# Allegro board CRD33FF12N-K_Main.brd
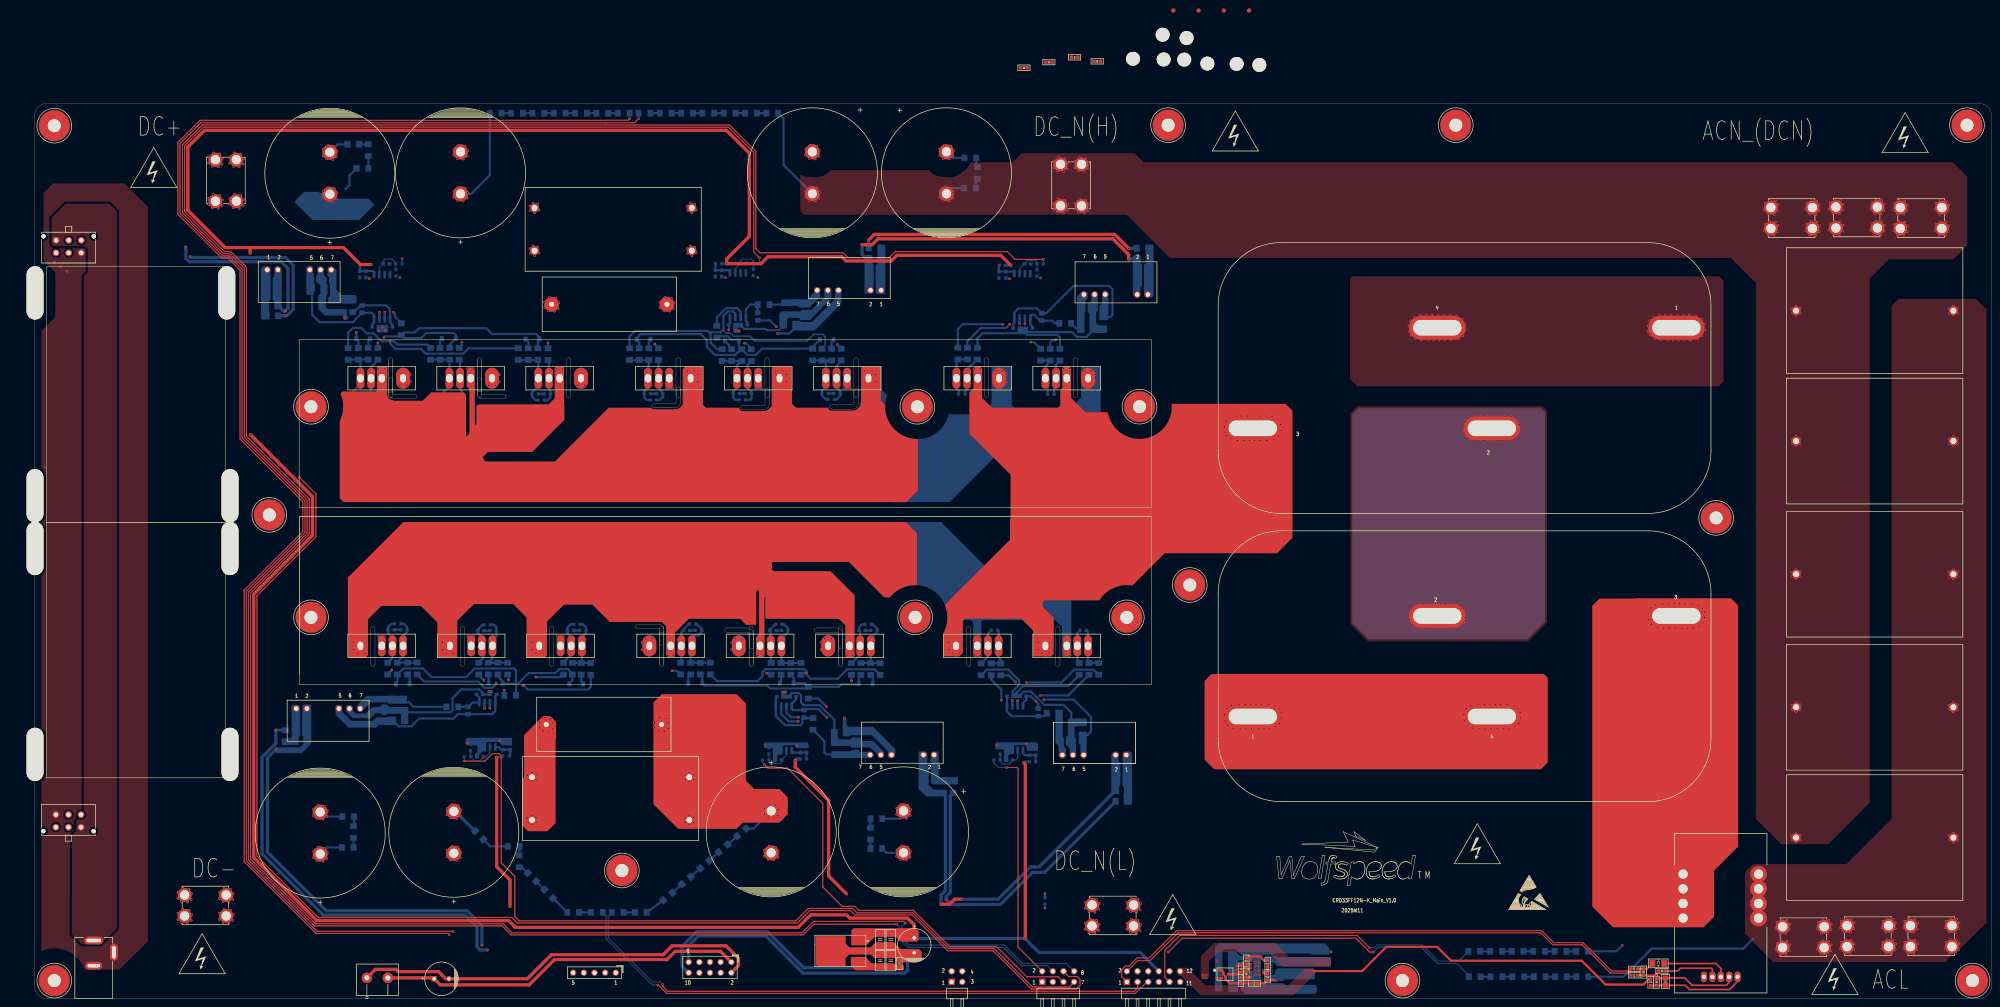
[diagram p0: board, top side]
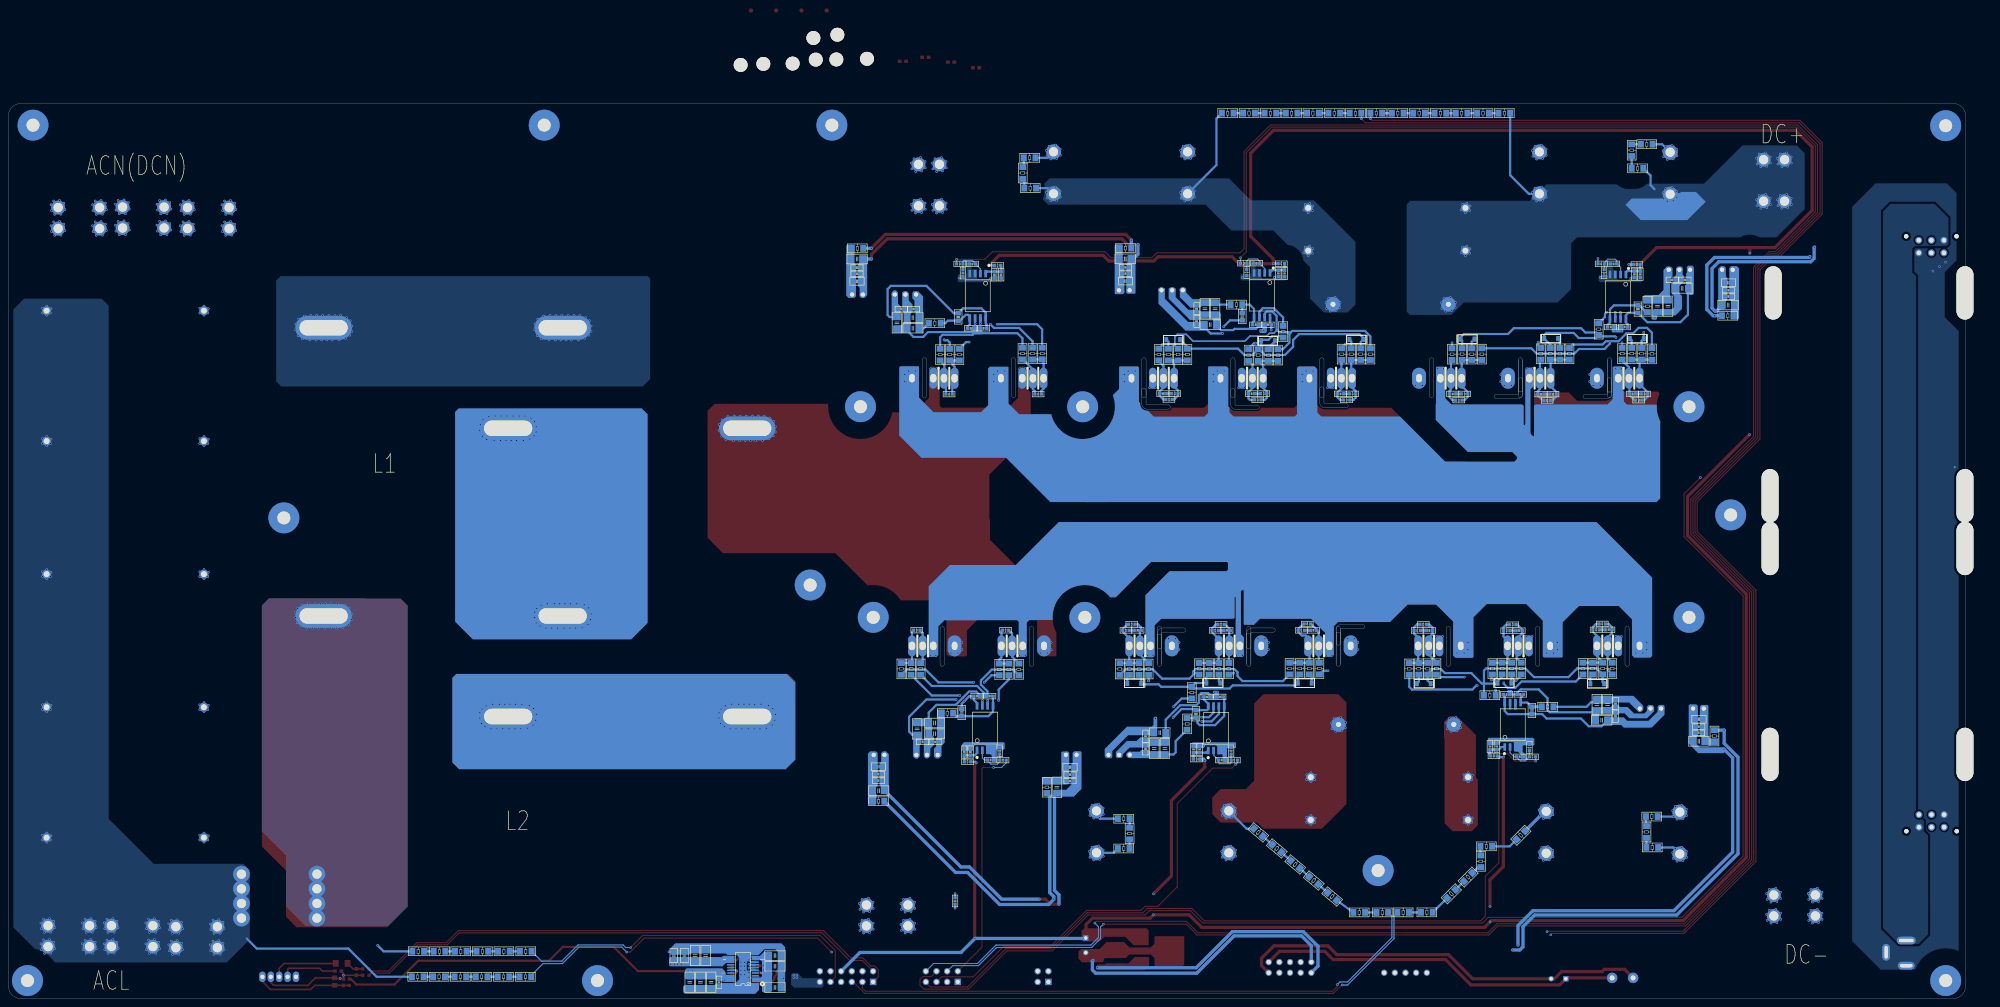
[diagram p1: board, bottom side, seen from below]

Outline 466.64 x 213.59 mm; copper layers: TOP, GND02, ART03, ART04, ART05, BOTTOM. Coordinates in mm from the lower left corner of the outline.

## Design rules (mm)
net group H_POWER: nets AC_L_SAMPLE AC_SW NETL1_2 NETL2_1

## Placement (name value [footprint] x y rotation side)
C1  C0603C104K5RAC7411  [C0603]  79 172.82 90 bottom
C2  C1608X7R1V105K080AE  [C0603]  77.55 172.82 270 bottom
C3  GRM1885C1H102GA01D  [C0603]  83.91 175.31 180 bottom
C4  C1608X7R1V225K080AE  [C0603]  84.62 160.22 0 bottom
C5  C2012X7R1H475K125AC  [C0805]  78.12 164.51 90 bottom
C7  C1608X7R1V225K080AE  [C0603]  81.3 160.22 0 bottom
C8  C0603C104K5RAC7411  [C0603]  231.6 172.68 90 bottom
C9  C1608X7R1V105K080AE  [C0603]  229.94 172.68 270 bottom
C10  GRM1885C1H102GA01D  [C0603]  236.8 175.28 180 bottom
C11  C0603C104K5RAC7411  [C0603]  163.87 173.02 90 bottom
C12  1U  [C0603]  237.18 159.93 180 bottom
C13  C1608X7R1V105K080AE  [C0603]  162.35 173.02 270 bottom
C14  GRM1885C1H102GA01D  [C0603]  169.07 175.46 180 bottom
C15  C1608X7R1V225K080AE  [C0603]  169.24 160.77 0 bottom
C16  2.2u  [C0805]  240.18 162.64 90 bottom
C17  C2012X7R1H475K125AC  [C0805]  172.46 162.72 90 bottom
C18  1U  [C0603]  234.13 159.93 180 bottom
C19  C0603C104K5RAC7411  [C0603]  79.39 144.27 180 bottom
C20  C1608X7R1V225K080AE  [C0603]  166.32 160.77 0 bottom
C21  C1608X7R1V225K080AE  [C0603]  177.8 71.99 180 bottom
C22  C0603C104K5RAC7411  [C0603]  182.6 59.46 270 bottom
C23  C1608X7R1V105K080AE  [C0603]  184.12 59.46 90 bottom
C24  GRM1885C1H102GA01D  [C0603]  177.37 56.91 0 bottom
C25  C2012X7R1H475K125AC  [C0805]  183.49 67.94 270 bottom
C26  C0603C104K5RAC7411  [C0603]  237.24 58.84 270 bottom
C27  C1608X7R1V105K080AE  [C0603]  238.77 58.84 90 bottom
C29  C1608X7R1V225K080AE  [C0603]  180.84 71.99 180 bottom
C30  C1608X7R1V225K080AE  [C0603]  106.2 72.59 180 bottom
C31  GRM1885C1H102GA01D  [C0603]  232.48 56.92 0 bottom
C32  1U  [C0603]  232.67 72.16 0 bottom
C33  2.2u  [C0805]  239.34 68.27 90 bottom
C34  C2012X7R1H475K125AC  [C0805]  103.41 68.76 90 bottom
C35  1U  [C0603]  235.71 72.16 0 bottom
C36  C0603C104K5RAC7411  [C0603]  111.75 60.15 270 bottom
C37  C1608X7R1V105K080AE  [C0603]  113.42 60.14 90 bottom
C38  GRM1885C1H102GA01D  [C0603]  106.31 57.7 0 bottom
C39  C0603C104K5RAC7411  [C0603]  122.27 144.27 180 bottom
C40  C1608X7R1V225K080AE  [C0603]  109.43 72.58 180 bottom
C43  820uF  [CAP2_1000-D3000X6000]  70.44 196.92 90 top
C44  820uF  [CAP2_1000-D3000X6000]  101.6 197.01 90 top
C45  820uF  [CAP2_1000-D3000X6000]  217.46 197.03 270 top
C46  820uF  [CAP2_1000-D3000X6000]  185.48 197.03 270 top
C47  15u  [CAPFILM_42X20MM]  137.99 183.55 0 top
C49  820uF  [CAP2_1000-D3000X6000]  175.67 39.78 270 top
C50  820uF  [CAP2_1000-D3000X6000]  207.21 39.78 270 top
C51  820uF  [CAP2_1000-D3000X6000]  100 39.68 90 top
C52  820uF  [CAP2_1000-D3000X6000]  68.14 39.5 90 top
C53  15u  [CAPFILM_42X20MM]  137.38 47.72 180 top
C54  C0603C104K5RAC7411  [C0603]  101.23 144.22 180 bottom
C55  2U  [CAPFILM_31_5X12_5MM]  137.07 165.66 0 top
C56  C0603C104K5RAC7411  [C0603]  253.38 223.63 0 top
C57  C0603C104K5RAC7411  [C0603]  248.01 224.59 0 top
C61  C0603C104K5RAC7411  [C0603]  241.87 223.44 0 top
C62  C0603C104K5RAC7411  [C0603]  235.92 222.09 0 top
C64  C0603C104K5RAC7411  [C0603]  149.04 144.3 180 bottom
C65  C0603C104K5RAC7411  [C0603]  191.38 144.37 180 bottom
C66  C0603C104K5RAC7411  [C0603]  170.22 144.35 180 bottom
C67  2u  [CAP2_3750-4200X3000X4500]  438.78 69.52 180 top
C70  C0603C104K5RAC7411  [C0603]  155.51 87.86 0 bottom
C71  2U  [CAPFILM_31_5X12_5MM]  135.78 65.41 180 top
C73  10U  [C1206]  201.65 9.04 270 top
C74  1U  [C0603]  206.22 8.41 270 top
C75  25V 220uF  [ECAP_D8P3_5]  209.77 12.73 270 top
C76  10U  [C1206]  204.19 9.04 270 top
C77  10U  [C1206]  201.65 14.12 90 top
C78  10U  [C1206]  204.19 14.12 90 top
C79  10u  [C1206]  299.11 3.91 270 bottom
C80  10u  [C1206]  304.19 3.91 270 bottom
C81  0.1u  [C0603]  297.2 3.91 270 bottom
C82  10u  [C1206]  301.65 3.91 270 bottom
C83  C1608X7R1V105K080AE  [C0603]  69.95 171.49 180 bottom
C84  C3216X7R1V475K160AB  [C1206]  73.45 165.21 90 bottom
C85  CMP-08246-001891-1  [C1206]  70.95 165.2 270 bottom
C86  CMP-08246-001891-1  [C1206]  56.63 165.47 0 bottom
C87  C1608X7R1V105K080AE  [C0603]  56.56 167.5 0 bottom
C88  C0603C104K5RAC7411  [C0603]  56.56 169.03 180 bottom
C89  C2012X7R1H225K125AC  [C0805]  56.56 170.8 0 bottom
C90  C1608X7R1V105K080AE  [C0603]  66.92 171.49 180 bottom
C91  CMP-08246-001891-1  [C1206]  67.6 169.45 180 bottom
C92  0.1u  [C0603]  288.95 5.82 270 top
C93  2.2u  [C0805]  305.46 10.26 90 bottom
C94  2.2u  [C0805]  308 10.26 90 bottom
C95  10u  [C1206]  300.38 10.26 90 bottom
C96  10u  [C1206]  302.92 10.26 90 bottom
C97  10u  [C1206]  283.87 10.26 180 bottom
C98  10u  [C1206]  283.87 7.72 180 bottom
C99  10u  [C1206]  283.87 2.64 180 bottom
C100  C1608X7R1V105K080AE  [C0603]  183.32 164.58 270 bottom
C101  C3216X7R1V475K160AB  [C1206]  178.95 164.59 90 bottom
C102  CMP-08246-001891-1  [C1206]  181.36 164.59 270 bottom
C103  CMP-08246-001891-1  [C1206]  200.38 176.51 180 bottom
C104  C1608X7R1V105K080AE  [C0603]  200.32 174.47 180 bottom
C105  C0603C104K5RAC7411  [C0603]  200.32 172.95 0 bottom
C106  C2012X7R1H225K125AC  [C0805]  200.32 171.17 180 bottom
C107  C1608X7R1V105K080AE  [C0603]  183.32 161.62 270 bottom
C108  CMP-08246-001891-1  [C1206]  180.11 160.8 0 bottom
C109  C1608X7R1V105K080AE  [C0603]  195.54 59.57 90 bottom
C110  C3216X7R1V475K160AB  [C1206]  190.9 59.65 270 bottom
C111  CMP-08246-001891-1  [C1206]  193.44 59.65 90 bottom
C112  CMP-08246-001891-1  [C1206]  216.63 50.44 270 bottom
C113  C1608X7R1V105K080AE  [C0603]  213.52 51.91 180 bottom
C114  C0603C104K5RAC7411  [C0603]  213.52 53.43 0 bottom
C115  C2012X7R1H225K125AC  [C0805]  213.52 55.21 180 bottom
C116  C1608X7R1V105K080AE  [C0603]  250.85 164.52 0 bottom
C117  C3216X7R1V475K160AB  [C1206]  250.98 162.49 180 bottom
C118  CMP-08246-001891-1  [C1206]  250.98 159.95 0 bottom
C119  C1608X7R1V105K080AE  [C0603]  195.54 62.59 90 bottom
C120  CMP-08246-001891-1  [C1206]  192.11 63.46 0 bottom
C121  CMP-08246-001891-1  [C1206]  264.29 176.46 180 bottom
C122  C1608X7R1V105K080AE  [C0603]  264.32 174.43 180 bottom
C123  C0603C104K5RAC7411  [C0603]  264.32 172.9 0 bottom
C124  C2012X7R1H225K125AC  [C0805]  264.32 171.12 180 bottom
C125  C1608X7R1V105K080AE  [C0603]  253.77 164.52 0 bottom
C126  CMP-08246-001891-1  [C1206]  254.79 161.22 90 bottom
C127  C1608X7R1V105K080AE  [C0603]  83.46 70.39 270 bottom
C128  C3216X7R1V475K160AB  [C1206]  87.92 70.16 90 bottom
C129  CMP-08246-001891-1  [C1206]  85.38 70.16 270 bottom
C130  CMP-08246-001891-1  [C1206]  63.59 61.39 0 bottom
C131  C1608X7R1V105K080AE  [C0603]  63.64 63.42 0 bottom
C132  C0603C104K5RAC7411  [C0603]  63.61 64.92 180 bottom
C133  C2012X7R1H225K125AC  [C0805]  63.57 66.66 0 bottom
C134  C1608X7R1V105K080AE  [C0603]  245.69 61.22 0 bottom
C135  C3216X7R1V475K160AB  [C1206]  245.82 65.76 180 bottom
C136  CMP-08246-001891-1  [C1206]  245.82 63.22 0 bottom
C137  C1608X7R1V105K080AE  [C0603]  83.46 67.38 270 bottom
C138  CMP-08246-001891-1  [C1206]  86.75 66.43 180 bottom
C139  CMP-08246-001891-1  [C1206]  259.14 49.62 180 bottom
C140  C1608X7R1V105K080AE  [C0603]  259.19 52.03 180 bottom
C141  C0603C104K5RAC7411  [C0603]  259.19 53.56 0 bottom
C142  C2012X7R1H225K125AC  [C0805]  259.19 55.33 180 bottom
C143  C1608X7R1V105K080AE  [C0603]  248.67 61.23 0 bottom
C144  CMP-08246-001891-1  [C1206]  249.98 64.36 270 bottom
C145  C0603C104K5RAC7411  [C0603]  197.35 87.86 0 bottom
C146  C0603C104K5RAC7411  [C0603]  176.13 87.85 0 bottom
C148  2u  [CAP2_3750-4200X3000X4500]  438.78 164.13 180 top
C149  2u  [CAP2_3750-4200X3000X4500]  438.78 133.02 180 top
C150  2u  [CAP2_3750-4200X3000X4500]  438.78 101.27 180 top
C151  2u  [CAP2_3750-4200X3000X4500]  438.78 38.4 180 top
C152  CL21B105KBFNNNG  [C0805]  388.88 4.06 90 top
C153  C0603C104K5RAC7411  [C0603]  386.74 3.92 90 top
C154  C0603C104K5RAC7411  [C0603]  388.03 6.58 180 top
C155  C0603C472K5RACAUTO  [C0603]  383.69 6.33 270 top
C157  25V 220uF  [ECAP_D8P3_5]  97.07 4.74 0 top
C162  C0603C104K5RAC7411  [C0603]  85.08 88 0 bottom
C163  C0603C104K5RAC7411  [C0603]  127.87 87.83 180 bottom
C164  C0603C104K5RAC7411  [C0603]  106.47 87.78 0 bottom
CON1  Connecter  [THREAD4_9P9X5_1110X920]  45.66 195.21 90 top
CON3  Connecter  [THREAD4_9P9X5_1110X920]  40.77 22.23 0 top
CON7  Connecter  [THREAD4_9P9X5_1110X920]  437.13 14.91 180 top
CON8  Connecter  [THREAD4_9P9X5_1110X920]  452.24 14.91 180 top
CON9  Connecter  [THREAD4_9P9X5_1110X920]  421.76 14.66 0 top
CON14  Connecter  [THREAD4_9P9X5_1110X920]  418.97 186.23 0 top
CON15  Connecter  [THREAD4_9P9X5_1110X920]  449.83 186.23 180 top
CON16  Connecter  [THREAD4_9P9X5_1110X920]  434.46 186.36 180 top
CON17  Connecter  [THREAD4_9P9X5_1110X920]  247.16 194.09 90 top
CON18  Connecter  [THREAD4_9P9X5_1110X920]  257.11 19.84 180 top
CON101  CON_3*2  [MOLEX_5557_6PIN]  11.12 40.89 180 top
CON102  CON_3*2  [MOLEX_5557_6PIN]  5.17 180.93 0 top
CON103  CON_3_1  [DC-005]  14.15 7.86 90 top
D1  SL14PL-TP  [SMDSOD123]  98.82 157.48 180 bottom
D2  SL14PL-TP  [SMDSOD123]  118.75 157.35 180 bottom
D3  SL14PL-TP  [SMDSOD123]  78.39 157.45 0 bottom
D6  SL14PL-TP  [SMDSOD123]  145.26 157.27 0 bottom
D7  SL14PL-TP  [SMDSOD123]  166.3 156.93 180 bottom
D8  SL14PL-TP  [SMDSOD123]  188.92 157.22 0 bottom
D9  SL14PL-TP  [SMDSOD123]  157.55 75.29 180 bottom
D10  SL14PL-TP  [SMDSOD123]  179.36 75.31 180 bottom
D13  SL14PL-TP  [SMDSOD123]  198.22 75.21 0 bottom
D14  SL14PL-TP  [SMDSOD123]  87.82 75.13 0 bottom
D15  SL14PL-TP  [SMDSOD123]  109.96 75.28 180 bottom
D16  SL14PL-TP  [SMDSOD123]  129.18 75.15 0 bottom
FD1  -  [FID1X2R]  283.58 235.75 0 top
FD2  -  [FID1X2R]  289.6 235.75 0 top
FD3  -  [FID1X2R]  277.56 235.75 0 top
FD4  -  [FID1X2R]  271.54 235.75 0 top
J1  CON_2*2  [HDR2X2H-254MM-90]  219.96 5.26 0 top
J2  CON2  [CON_5MM_2X1]  81.77 4.95 0 top
J3  CON_4*2  [HDR2X4H-254MM-90]  244.09 5.26 0 top
J4  CON5  [CON_2MM54_5X1]  133.54 6.17 180 top
J5  CON10A  [CON_2MM54_5X2]  161.08 7.44 180 top
J6  J10  [HDR2X6H-254MM-90]  266.82 5.26 0 top
L1  70uH Inv inductor  [L_116X64X60]  340.98 148.06 180 top
L2  70uH Inv inductor  [L_116X64X60]  340.98 79.3 0 top
MT1  Mouting Hole  [MTG330N]  274.15 224.03 180 bottom
MT2  Mouting Hole  [MTG330N]  274.71 229.18 0 top
MT3  Mouting Hole  [MTG330N]  269.24 224.06 0 top
MT4  Mouting Hole  [MTG330N]  279.66 223.09 180 bottom
MT5  Mouting Hole  [MTG330N]  261.93 224.23 180 bottom
MT6  Mouting Hole  [MTG330N]  268.99 229.97 0 top
MT7  Mouting Hole  [MTG330N]  286.65 223.01 0 top
MT8  Mouting Hole  [MTG330N]  292.06 222.76 270 top
NOREF  #VAL  [unnamed]  326.17 4.3 0 top
NOREF#2  #VAL  [unnamed]  39.62 9.57 0 top
NOREF#3  -  [#2]  436.25 -21 0 top
NOREF#4  #VAL  [unnamed]  428.94 4.64 0 top
NOREF#5  #VAL  [unnamed]  209.99 90.96 90 top
NOREF#6  #VAL  [unnamed]  65.95 90.97 270 top
NOREF#7  -  [#2]  6.87 -5 90 top
NOREF#8  -  [unnamed#3]  46.63 58.26 0 top
NOREF#9  -  [unnamed#3]  0.15 107.4 0 top
NOREF#10  #VAL  [unnamed]  271.05 18.91 0 top
NOREF#11  #VAL  [unnamed]  460.77 208.39 270 top
NOREF#12  -  [unnamed#3]  0.15 119.99 0 top
NOREF#13  #VAL  [unnamed]  338.89 208.39 270 top
NOREF#14  -  [unnamed#3]  46.63 119.99 0 top
NOREF#15  -  [#2]  356.34 24.41 0 top
NOREF#16  -  [#2]  326.01 -114.07 0 top
NOREF#17  #VAL  [unnamed]  263.48 141.22 270 top
NOREF#18  #VAL  [unnamed]  4.74 4.3 0 top
NOREF#19  #VAL  [unnamed]  462.09 4.3 0 top
NOREF#20  #VAL  [unnamed]  260.45 90.96 90 top
NOREF#21  #VAL  [unnamed]  343.67 35.8 0 top
NOREF#22  -  [unnamed#3]  46.63 107.4 0 top
NOREF#23  #VAL  [unnamed]  28.11 197.13 0 top
NOREF#24  -  [#2]  0 4.96 0 top
NOREF#25  #VAL  [unnamed]  285.97 205.86 0 top
NOREF#26  #VAL  [unnamed]  210.51 141.21 270 top
NOREF#27  -  [#2]  355.61 100.47 0 top
NOREF#28  -  [unnamed#3]  45.87 168.37 0 top
NOREF#29  #VAL  [unnamed]  270.31 208.39 270 top
NOREF#30  #VAL  [unnamed]  400.96 114.7 0 top
NOREF#31  #VAL  [unnamed]  4.74 208.26 0 top
NOREF#32  -  [unnamed#3]  0.15 58.26 0 top
NOREF#33  #VAL  [unnamed]  140.07 30.57 0 top
NOREF#34  #VAL  [unnamed]  445.67 205.47 0 top
NOREF#35  #VAL  [unnamed]  65.95 141.21 270 top
NOREF#36  -  [unnamed#3]  0.15 168.37 0 top
NOREF#37  #VAL  [unnamed]  275.47 98.68 270 top
NOREF#38  #VAL  [unnamed]  56.01 115.4 270 top
Q11  C3M0040120K  [TO-247-4L]  82.81 148.01 180 top
Q12  C3M0040120K  [TO-247-4L]  104.02 148.01 180 top
Q13  C3M0040120K  [TO-247-4L]  125.23 148.01 180 top
Q15  2N7002/SOT  [SOT-23]  283.87 5.82 270 top
Q21  C3M0040120K  [TO-247-4L]  151.36 148.01 180 top
Q22  C3M0040120K  [TO-247-4L]  172.57 148.01 180 top
Q23  C3M0040120K  [TO-247-4L]  193.78 148.01 180 top
Q31  C3M0040120K  [TO-247-4L]  151.7 84.16 0 top
Q32  C3M0040120K  [TO-247-4L]  173.01 84.16 0 top
Q33  C3M0040120K  [TO-247-4L]  194.33 84.16 0 top
Q41  C3M0040120K  [TO-247-4L]  82.81 84.16 0 top
Q42  C3M0040120K  [TO-247-4L]  104.13 84.16 0 top
Q43  C3M0040120K  [TO-247-4L]  125.45 84.16 0 top
Q51  C3M0021120K  [TO-247-4L]  224.91 148.01 180 top
Q52  C3M0021120K  [TO-247-4L]  246.12 148.01 180 top
Q61  C3M0021120K  [TO-247-4L]  224.81 84.16 0 top
Q62  C3M0021120K  [TO-247-4L]  246.12 84.16 0 top
R1  10R  [R1206]  96.73 153.84 90 bottom
R2  6R8  [R1206]  99.01 153.84 270 bottom
R3  AC0603FR-0710RL  [R0603]  78.37 175.13 180 bottom
R4  RMCF1206FT2R00  [R1206]  115.35 153.77 90 bottom
R5  RMCF1206FT2R00  [R1206]  94.44 153.84 90 bottom
R6  10R  [R1206]  117.76 153.77 90 bottom
R7  RMCF0603FT100R  [R0603]  86.9 175.31 180 bottom
R8  6R8  [R1206]  120.03 153.77 270 bottom
R9  10R  [R1206]  79.61 153.87 90 bottom
R10  RMCF0603FT4K70  [R0603]  86.19 173.15 90 bottom
R11  6R8  [R1206]  77.25 153.84 270 bottom
R12  RMCF1206FT1R00  [R1206]  81.89 153.87 90 bottom
R14  RMCF1206FT1R00  [R1206]  101.3 153.84 90 bottom
R15  RMCF1206FT2R00  [R1206]  239.9 153.64 90 bottom
R16  RMCF1206FT2R00  [R1206]  220.17 153.9 90 bottom
R17  RMCF1206FT2R00  [R1206]  74.79 153.82 90 bottom
R18  6R8  [R1206]  222.45 153.89 270 bottom
R19  AC0603FR-0710RL  [R0603]  230.81 174.95 180 bottom
R21  RMCF0603FT100R  [R0603]  239.8 175.29 180 bottom
R22  6R8  [R1206]  87.48 159.73 270 bottom
R23  6R8  [R1206]  242.21 153.64 270 bottom
R24  RMCF1206FT1R00  [R1206]  122.45 153.77 90 bottom
R25  RMCF0603FT4K70  [R0603]  239.05 173.11 90 bottom
R26  AC0603FR-0710RL  [R0603]  163.15 175.34 180 bottom
R27  10R  [R1206]  146.48 153.77 90 bottom
R28  6R8  [R1206]  144.19 153.77 270 bottom
R29  10R  [R1206]  166.23 153.54 90 bottom
R30  RMCF0603FT100R  [R0603]  172.12 175.45 180 bottom
R31  6R8  [R1206]  168.65 153.54 270 bottom
R32  RMCF1206FT1R00  [R1206]  224.86 153.89 90 bottom
R33  RMCF0603FT4K70  [R0603]  171.4 173.25 90 bottom
R34  RMCF1206FT1R00  [R1206]  244.5 153.64 90 bottom
R35  RMCF1206FT2R00  [R1206]  187.78 153.66 90 bottom
R36  RMCF1206FT2R00  [R1206]  163.95 153.54 90 bottom
R37  RMCF1206FT2R00  [R1206]  141.91 153.77 90 bottom
R38  10R  [R1206]  190.07 153.66 90 bottom
R39  6R8  [R1206]  162.71 159.11 270 bottom
R40  6R8  [R1206]  185.54 153.66 270 bottom
R41  AC0603FR-0710RL  [R0603]  183.33 57.13 0 bottom
R42  RMCF1206FT1R00  [R1206]  148.77 153.77 90 bottom
R43  RMCF1206FT1R00  [R1206]  170.94 153.54 90 bottom
R44  RMCF1206FT1R00  [R1206]  192.35 153.66 90 bottom
R45  10R  [R1206]  156.47 78.74 270 bottom
R46  RMCF0603FT100R  [R0603]  174.34 56.89 0 bottom
R48  6R8  [R1206]  158.76 78.74 90 bottom
R49  RMCF1206FT2R00  [R1206]  253.73 78.67 270 bottom
R50  RMCF1206FT2R00  [R1206]  230.39 78.55 270 bottom
R51  10R  [R1206]  178.03 78.69 270 bottom
R52  RMCF0603FT4K70  [R0603]  175.12 59.1 270 bottom
R53  6R8  [R1206]  228.13 78.56 90 bottom
R54  AC0603FR-0710RL  [R0603]  237.96 56.49 0 bottom
R55  6R8  [R1206]  180.33 78.69 90 bottom
R57  RMCF0603FT100R  [R0603]  229.5 56.89 0 bottom
R58  RMCF1206FT2R00  [R1206]  201.64 78.64 270 bottom
R59  6R8  [R1206]  251.42 78.67 90 bottom
R60  RMCF0603FT4K70  [R0603]  230.29 59.11 270 bottom
R61  RMCF1206FT1R00  [R1206]  225.72 78.56 270 bottom
R62  RMCF1206FT2R00  [R1206]  182.74 78.69 270 bottom
R63  RMCF1206FT1R00  [R1206]  249.15 78.66 270 bottom
R64  RMCF1206FT2R00  [R1206]  161.18 78.74 270 bottom
R65  AC0603FR-0710RL  [R0603]  112.45 57.9 0 bottom
R66  10R  [R1206]  199.36 78.64 270 bottom
R67  6R8  [R1206]  184.5 72.99 90 bottom
R68  6R8  [R1206]  197.07 78.64 90 bottom
R69  RMCF1206FT1R00  [R1206]  154.07 78.74 270 bottom
R70  RMCF0603FT100R  [R0603]  103.26 57.69 0 bottom
R71  RMCF1206FT1R00  [R1206]  175.64 78.69 270 bottom
R72  RMCF0603FT4K70  [R0603]  103.99 59.9 270 bottom
R73  RMCF1206FT1R00  [R1206]  194.79 78.64 270 bottom
R74  10R  [R1206]  88.95 78.75 270 bottom
R75  0R3J  [R0603]  381.41 7.09 0 top
R76  0R3J  [R0603]  381.41 5.57 0 top
R77  6R8  [R1206]  86.54 78.75 90 bottom
R78  10R  [R1206]  108.23 78.74 270 bottom
R79  6R8  [R1206]  110.51 78.74 90 bottom
R80  RMCF1206FT2R00  [R1206]  132.65 78.66 270 bottom
R81  470K  [R1206]  140.51 211.25 0 bottom
R82  470K  [R1206]  145.46 211.26 180 bottom
R83  ERJ-3EKF1002V  [R0603]  221.13 144.23 180 bottom
R84  RMCF1206FT2R00  [R1206]  112.82 78.71 270 bottom
R85  ERJ-3EKF1002V  [R0603]  242.36 144.23 180 bottom
R86  470K  [R1206]  106.04 38.98 315 bottom
R87  470K  [R1206]  168.63 39.65 220 bottom
R88  ERJ-3EKF1002V  [R0603]  228.89 87.88 0 bottom
R89  ERJ-3EKF1002V  [R0603]  250.05 87.9 0 bottom
R90  RMCF1206FT2R00  [R1206]  91.24 78.75 270 bottom
R91  RC0603FR-072RL  [R0603]  76.55 144.27 180 bottom
R92  RC0603FR-072RL  [R0603]  119.42 144.27 180 bottom
R93  RC0603FR-072RL  [R0603]  98.36 144.22 180 bottom
R94  ERJ-3EKF1002V  [R0603]  77.94 142.77 180 bottom
R95  10R  [R1206]  130.37 78.69 270 bottom
R96  6R8  [R1206]  113.43 72.38 0 bottom
R97  0R3J  [R0603]  385.34 3.92 90 top
R98  RMCF1206FT10R0  [R1206]  387.17 8.4 0 top
R99  0R3J  [R0603]  240.93 23.3 270 bottom
R100  470K  [R1206]  175.93 211.26 180 bottom
R101  470K  [R1206]  170.85 211.26 180 bottom
R102  470K  [R1206]  165.77 211.26 180 bottom
R103  470K  [R1206]  160.69 211.26 180 bottom
R104  470K  [R1206]  155.61 211.26 180 bottom
R105  470K  [R1206]  150.53 211.26 180 bottom
R106  470K  [R1206]  114.28 36.32 0 bottom
R107  470K  [R1206]  115.57 32.77 270 bottom
R108  470K  [R1206]  118.61 29 315 bottom
R109  470K  [R1206]  109.99 211.25 0 bottom
R110  470K  [R1206]  115.07 211.25 0 bottom
R111  470K  [R1206]  120.15 211.25 0 bottom
R112  470K  [R1206]  125.23 211.25 0 bottom
R113  470K  [R1206]  130.31 211.25 0 bottom
R114  470K  [R1206]  135.39 211.25 0 bottom
R115  470K  [R1206]  122.61 25 315 bottom
R116  470K  [R1206]  128.44 20.58 0 bottom
R117  470K  [R1206]  134.1 20.57 0 bottom
R118  RC0603FR-072RL  [R0603]  178.92 87.85 0 bottom
R120  470K  [R1206]  164.23 35.83 220 bottom
R121  6R8  [R1206]  128.26 78.7 90 bottom
R122  RMCF1206FT1R00  [R1206]  84.25 78.75 270 bottom
R123  RMCF1206FT1R00  [R1206]  105.94 78.74 270 bottom
R124  RMCF1206FT1R00  [R1206]  126.16 78.7 270 bottom
R125  470K  [R1206]  78.23 198.09 0 bottom
R126  470K  [R1206]  79.61 202.43 90 bottom
R127  470K  [R1206]  76.01 203.83 180 bottom
R128  470K  [R1206]  223.15 200.6 0 bottom
R129  470K  [R1206]  224.8 196.98 270 bottom
R130  470K  [R1206]  223.02 193.37 180 bottom
R131  470K  [R1206]  200.72 42.93 180 bottom
R132  470K  [R1206]  199.32 39.37 270 bottom
R133  620K  [R1206]  369.04 5.22 180 bottom
R134  620K  [R1206]  363.96 5.22 180 bottom
R135  620K  [R1206]  358.88 5.22 180 bottom
R136  620K  [R1206]  353.8 5.22 180 bottom
R137  620K  [R1206]  348.59 5.22 180 bottom
R138  620K  [R1206]  343.39 5.22 180 bottom
R139  620K  [R1206]  368.94 11.29 180 bottom
R140  620K  [R1206]  363.86 11.29 180 bottom
R141  620K  [R1206]  358.78 11.29 180 bottom
R142  620K  [R1206]  353.63 11.28 180 bottom
R143  620K  [R1206]  348.49 11.29 180 bottom
R144  620K  [R1206]  343.29 11.29 180 bottom
R145  10K  [R0603]  287.68 7.09 90 top
R146  100K  [R0603]  294.03 5.18 90 top
R147  RMCF1206FT1R00  [R1206]  56.69 162.93 180 bottom
R148  0  [R0603]  294.03 8.36 270 top
R149  1.5K  [R0603]  290.88 3.63 0 top
R150  0  [R0603]  288.95 8.99 270 top
R151  12K  [R0603]  287.68 4.27 270 top
R152  RMCF1206FT1R00  [R1206]  200.32 179.05 0 bottom
R153  RMCF1206FT1R00  [R1206]  219.06 50.45 90 bottom
R154  RMCF1206FT1R00  [R1206]  264.24 179 0 bottom
R155  RMCF1206FT1R00  [R1206]  59.88 62.65 270 bottom
R156  RMCF1206FT1R00  [R1206]  259.19 47.08 0 bottom
R157  470K  [R1206]  159.82 32.01 220 bottom
R158  470K  [R1206]  155.42 28.19 220 bottom
R159  470K  [R1206]  151.02 24.36 220 bottom
R160  470K  [R1206]  144.57 20.56 180 bottom
R161  470K  [R1206]  139.07 20.56 180 bottom
R165  470K  [R1206]  200.72 35.81 0 bottom
R166  470K  [R1206]  76.08 39.75 270 bottom
R167  470K  [R1206]  74.72 36.07 180 bottom
R168  470K  [R1206]  74.81 43.43 0 bottom
R169  ERJ-3EKF1002V  [R0603]  120.82 142.78 180 bottom
R170  ERJ-3EKF1002V  [R0603]  189.93 142.95 180 bottom
R171  ERJ-3EKF1002V  [R0603]  198.79 89.31 0 bottom
R172  ERJ-3EKF1002V  [R0603]  129.33 89.31 0 bottom
R173  ERJ-3EKF1002V  [R0603]  99.76 142.72 180 bottom
R174  RC0603FR-072RL  [R0603]  146.17 144.3 180 bottom
R175  RC0603FR-072RL  [R0603]  188.53 144.37 180 bottom
R176  RC0603FR-072RL  [R0603]  167.35 144.35 180 bottom
R177  ERJ-3EKF1002V  [R0603]  147.59 142.82 180 bottom
R178  ERJ-3EKF1002V  [R0603]  168.75 142.85 180 bottom
R179  RC0603FR-072RL  [R0603]  158.36 87.86 0 bottom
R180  RC0603FR-072RL  [R0603]  200.19 87.86 0 bottom
R182  ERJ-3EKF1002V  [R0603]  156.96 89.38 0 bottom
R183  ERJ-3EKF1002V  [R0603]  177.52 89.29 0 bottom
R184  RC0603FR-072RL  [R0603]  88.1 87.99 0 bottom
R185  RC0603FR-072RL  [R0603]  130.75 87.83 0 bottom
R186  RC0603FR-072RL  [R0603]  109.39 87.78 0 bottom
R187  ERJ-3EKF1002V  [R0603]  86.63 89.4 0 bottom
R188  ERJ-3EKF1002V  [R0603]  107.97 89.2 0 bottom
R189  RMCF1206FT1R00  [R1206]  75.86 165.19 270 bottom
R190  RMCF1206FT1R00  [R1206]  245.75 161.14 180 bottom
R191  RMCF1206FT1R00  [R1206]  173.85 165.58 180 bottom
R192  RMCF1206FT1R00  [R1206]  242.79 68.11 180 bottom
R193  RMCF1206FT1R00  [R1206]  185.63 65.54 90 bottom
R194  RMCF1206FT1R00  [R1206]  99.65 69.62 0 bottom
U1  UCC5350MCQDWV  [SOIC8_DWV]  82.89 167.46 270 bottom
U2  UCC5350MCQDWV  [SOIC8_DWV]  235.53 167.68 270 bottom
U3  UCC5350MCQDWV  [SOIC8_DWV]  167.74 167.84 270 bottom
U4  UCC5350MCQDWV  [SOIC8_DWV]  178.67 64.49 90 bottom
U5  UCC5350MCQDWV  [SOIC8_DWV]  233.79 64.55 90 bottom
U6  UCC5350MCQDWV  [SOIC8_DWV]  107.97 65.33 90 bottom
U8  LF50ABDT-TR  [TO252AB]  189.24 11.42 90 top
U9  TPS70445PWP_TSSOP24  [TSSOP24]  291.49 7.09 0 bottom
U11  R15P21503D  [G1212S_2W11]  63.15 171.79 0 top
U12  R15P21503D  [G1212S_2W11]  194.26 171.1 180 top
U13  R15P21503D  [G1212S_2W11]  206.89 60.26 180 top
U14  R15P21503D  [G1212S_2W11]  257.85 170.09 180 top
U15  R15P21503D  [G1212S_2W11]  70.05 67.1 0 top
U16  HOB 130-P/SP33  [CT13_HOB-P_SP33]  402.08 5.2 270 top
U17  R15P21503D  [G1212S_2W11]  252.7 60.24 180 top

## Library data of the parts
C1-C4 C7-C15 C18-C24 C26 C27 C29-C32 C35-C40 C54 C56 C57 C61 C62 C64-C66 C70 C74 C81 C83 C87 C88 C90 C92 C100 C104 C105 C107 C109 C113 C114 C116 C119 C122 C123 C125 C127 C131 C132 C134 C137 C140 C141 C143 C145 C146 C153-C155 C162-C164 = C0603: User Part Number: HAMP; Tolerance: #TOL
C5 C16 C17 C25 C33 C34 C89 C93 C94 C106 C115 C124 C133 C142 C152 = C0805: User Part Number: HAMP; Tolerance: #TOL
C43-C46 C49-C52 = CAP2_1000-D3000X6000: User Part Number: HAMP; Tolerance: #TOL
C47 C53 = CAPFILM_42X20MM: Tolerance: #TOL; User Part Number: HAMP
C55 C71 = CAPFILM_31_5X12_5MM: User Part Number: HAMP; Tolerance: #TOL
C67 C148-C151 = CAP2_3750-4200X3000X4500: Tolerance: #TOL; User Part Number: HAMP
C73 C76-C80 C82 C84-C86 C91 C95-C99 C101-C103 C108 C110-C112 C117 C118 C120 C121 C126 C128-C130 C135 C136 C138 C139 C144 = C1206: User Part Number: HAMP; Tolerance: #TOL
C75 C157 = ECAP_D8P3_5: User Part Number: HAMP; Tolerance: #TOL
CON1 CON3 CON7-CON9 CON14-CON18 = THREAD4_9P9X5_1110X920: Tolerance: #TOL; User Part Number: HAMP
CON101 CON102 = MOLEX_5557_6PIN: User Part Number: HAMP; Tolerance: #TOL
CON103 = DC-005: User Part Number: HAMP; Tolerance: #TOL
D1-D3 D6-D10 D13-D16 = SMDSOD123: Tolerance: #TOL; User Part Number: HAMP
FD1-FD4 = FID1X2R: Tolerance: #TOL; User Part Number: HAMP
J1 = HDR2X2H-254MM-90: User Part Number: HAMP; Tolerance: #TOL
J2 = CON_5MM_2X1: User Part Number: HAMP; Tolerance: #TOL
J3 = HDR2X4H-254MM-90: User Part Number: HAMP; Tolerance: #TOL
J4 = CON_2MM54_5X1: User Part Number: HAMP; Tolerance: #TOL
J5 = CON_2MM54_5X2: Tolerance: #TOL; User Part Number: HAMP
J6 = HDR2X6H-254MM-90: User Part Number: HAMP; Tolerance: #TOL
L1 L2 = L_116X64X60: Tolerance: #TOL; User Part Number: HAMP
MT1-MT8 = MTG330N: Tolerance: #TOL; User Part Number: HAMP
NOREF NOREF#2 NOREF#4-NOREF#6 NOREF#10 NOREF#11 NOREF#17-NOREF#21 NOREF#25 NOREF#26 NOREF#29-NOREF#31 NOREF#33-NOREF#35 NOREF#37 NOREF#38 = -: Tolerance: #TOL; User Part Number: HAMP
NOREF#13 NOREF#23 = -: User Part Number: HAMP; Tolerance: #TOL
Q11-Q13 Q21-Q23 Q31-Q33 Q41-Q43 Q51 Q52 Q61 Q62 = TO-247-4L: Tolerance: #TOL; User Part Number: HAMP
Q15 = SOT-23: User Part Number: HAMP; Tolerance: #TOL
R1 R2 R4-R6 R8 R9 R11 R12 R14-R18 R22-R24 R27-R29 R31 R32 R34-R40 R42-R45 R48-R51 R53 R55 R58 R59 R61-R64 R66-R69 R71 R73 R74 R77-R82 R84 R86 R87 R90 R95 R96 R98 R100-R117 R120-R144 R147 R152-R161 R165-R168 R189-R194 = R1206: User Part Number: HAMP; Tolerance: #TOL
R3 R7 R10 R19 R21 R25 R26 R30 R33 R41 R46 R52 R54 R57 R60 R65 R70 R72 R75 R76 R83 R85 R88 R89 R91-R94 R97 R99 R118 R145 R146 R148-R151 R169-R180 R182-R188 = R0603: User Part Number: HAMP; Tolerance: #TOL
U1-U6 = SOIC8_DWV: User Part Number: HAMP; Tolerance: #TOL
U8 = TO252AB: User Part Number: HAMP; Tolerance: #TOL
U9 = TSSOP24: Tolerance: #TOL; User Part Number: HAMP
U11-U15 U17 = G1212S_2W11: Tolerance: #TOL; User Part Number: HAMP
U16 = CT13_HOB-P_SP33: Tolerance: #TOL; User Part Number: HAMP

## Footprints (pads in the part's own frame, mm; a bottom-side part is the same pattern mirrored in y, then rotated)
C0603
  rect 0.889x0.787 smd: 1(-0.76,0) 2(0.76,0)
C0805
  rect 1.092x1.27 smd: 1(-0.89,0) 2(0.89,0)
C1206
  rect 1.397x1.6 smd: 1(-1.4,0) 2(1.4,0)
CAP2_1000-D3000X6000
  round 3.556 hole 2.184: 1(-5,0) 2(5,0)
CAP2_3750-4200X3000X4500
  round 2.159 hole 1.397: 1(-18.75,0) 2(18.75,0)
CAPFILM_31_5X12_5MM
  round 3.505 hole 1.194: 1(-13.75,0) 2(13.75,0)
CAPFILM_42X20MM
  round 2.159 hole 1.397: 1(-18.75,5.1) 2(18.75,5.1) 3(-18.75,-5.1) 4(18.75,-5.1)
CON_2MM54_5X1
  round 1.499 hole 1.016: 1(-5.08,0) 2(-2.54,0) 3(0,0) 4(2.54,0) 5(5.08,0)
CON_2MM54_5X2
  round 1.499 hole 1.016: 1(-5.08,-1.27) 2(-5.08,1.27) 3(-2.54,-1.27) 4(-2.54,1.27) 5(0,-1.27) 6(0,1.27) 7(2.54,-1.27) 8(2.54,1.27) 9(5.08,-1.27) 10(5.08,1.27)
CON_5MM_2X1
  round 2.489 hole 1.194: 1(-2.5,0) 2(2.5,0)
CT13_HOB-P_SP33
  oval 2.489x1.524 hole 1.016: 1(0,4) 2(0,2) 3(0,0) 4(0,-2) 5(0,-4)
  round 3.988 hole 2.21: 6(-14,-9) 7(-17.5,-9) 8(-21,-9) 9(-24.5,-9) 10(-24.5,9) 11(-21,9) 12(-17.5,9) 13(-14,9)
DC-005
  oval 1.829x4.521 hole 0.813x3.505: 1(6,0)
  oval 1.829x4.013 hole 0.813x2.997: 2(0,0)
  oval 4.013x1.829 hole 2.997x0.813: 3(3.2,-4.8)
ECAP_D8P3_5
  rect 1.27x1.27 hole 0.813: 1(-1.75,0)
  round 1.27 hole 0.813: 2(1.75,0)
FID1X2R
  round 1.016 smd: 0(0,0)
G1212S_2W11
  round 1.499 hole 1.016: 1(-7.62,2.1) 2(-5.08,2.1) 5(2.54,2.1) 6(5.08,2.1) 7(7.62,2.1)
HDR2X2H-254MM-90
  rect 1.524x1.524 hole 1.016: 1(-1.27,-1.27)
  round 1.524 hole 1.016: 2(-1.27,1.27) 3(1.27,-1.27) 4(1.27,1.27)
HDR2X4H-254MM-90
  rect 1.524x1.524 hole 1.016: 1(-3.81,-1.27)
  round 1.524 hole 1.016: 2(-3.81,1.27) 3(-1.27,-1.27) 4(-1.27,1.27) 5(1.27,-1.27) 6(1.27,1.27) 7(3.81,-1.27) 8(3.81,1.27)
HDR2X6H-254MM-90
  rect 1.524x1.524 hole 1.016: 1(-6.35,-1.27)
  round 1.524 hole 1.016: 2(-6.35,1.27) 3(-3.81,-1.27) 4(-3.81,1.27) 5(-1.27,-1.27) 6(-1.27,1.27) 7(1.27,-1.27) 8(1.27,1.27) 9(3.81,-1.27) 10(3.81,1.27) 11(6.35,-1.27) 12(6.35,1.27)
L_116X64X60
  oval 13.5x5.7 hole 11.5x3.7: 1(-50.5,-12) 2(-6.5,12) 3(50.5,12) 4(6.5,-12)
MOLEX_5557_6PIN
  round 1.041 hole 1.041 unplated: (-3,0.95) (9,0.95)
  round 1.651 hole 1.041: 1(6,-3) 2(6,0) 3(3,-3) 4(3,0) 5(0,-3) 6(0,0)
MTG330N
  round 3.3 hole 3.3 unplated: (0,0)
R0603
  rect 0.762x0.762 smd: 1(-0.76,0) 2(0.76,0)
R1206
  rect 1.397x1.6 smd: 1(-1.4,0) 2(1.4,0)
SMDSOD123
  rect 0.914x1.219 smd: 1(1.651,0) 2(-1.651,0)
SOIC8_DWV
  rect 1.778x0.635 smd: 1(-5.3,1.905) 2(-5.3,0.635) 3(-5.3,-0.635) 4(-5.3,-1.905) 5(5.3,-1.905) 6(5.3,-0.635) 7(5.3,0.635) 8(5.3,1.905)
SOT-23
  oval 0.61x1.27 smd: 1(-0.95,-1.01) 2(0.95,-1.01) 3(0,1.01)
THREAD4_9P9X5_1110X920
  round 3.302 hole 2.21: 1(4.95,2.5) 2(-4.95,2.5) 3(-4.95,-2.5) 4(4.95,-2.5)
TO252AB
  rect 1.6x2.997 smd: 1(2.3,-7.16) 3(-2.3,-7.16)
  rect 6.706x6.706 smd: 2(0,-0.51)
TO-247-4L
  oval 3.302x5.004 hole 1.346x2.007: 1(-5.08,0)
  oval 1.829x4.978 hole 1.524x2.032: 2(0,0) 3(2.54,0) 4(5.08,0)
TSSOP24
  oval 1.778x0.381 smd: 1(-2.925,3.575) 2(-2.925,2.925) 3(-2.925,2.275) 4(-2.925,1.625) 5(-2.925,0.975) 6(-2.925,0.325) 7(-2.925,-0.325) 8(-2.925,-0.975) 9(-2.925,-1.625) 10(-2.925,-2.275) 11(-2.925,-2.925) 12(-2.925,-3.575) 13(2.925,-3.575) 14(2.925,-2.925) 15(2.925,-2.275) 16(2.925,-1.625) 17(2.925,-0.975) 18(2.925,-0.325) 19(2.925,0.325) 20(2.925,0.975) 21(2.925,1.625) 22(2.925,2.275) 23(2.925,2.925) 24(2.925,3.575)
  rect 1.651x3.937 smd: 25(0,0)
unnamed
  round 7.366 hole 3.099: 1(0,0)
unnamed#3
  oval 4.013x12.7 hole 4.013x12.7 unplated: (0,0)

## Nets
+14V: C157.1 J2.2 J5.1
AGND: C1.1 C2.2 C3.1 C8.1 C9.2 C10.1 C11.1 C13.2 C14.1 C22.1 C23.2 C24.1 C26.1 C27.2 C31.1 C36.1 C37.2 C38.1 C73.1 C74.1 C75.2 C76.1 C77.1 C78.1 C79.2 C80.2 C81.2 C82.2 C92.2 C93.2 C94.2 C95.2 C96.2 C97.2 C98.2 C99.2 C152.2 C153.2 C154.2 C155.2 J3.3 J5.9 J6.10 Q15.2 R10.1 R25.1 R33.1 R52.1 R60.1 R72.1 R76.2 R99.2 R151.1 U1.3 U1.4 U2.3 U2.4 U3.3 U3.4 U4.3 U4.4 U5.3 U5.4 U6.3 U6.4 U8.2 U9.1 U9.6 U9.9 U9.12 U9.13 U9.24 U9.25 U16.2
P6.5V: C73.2 C74.2 C76.2 J5.10 U8.3
P15V: J5.5 R147.1 R152.1 R153.1 R154.1 R155.1 R156.1
SGND: J4.5
A_1.2V: C93.1 C94.1 C95.1 C96.1 J6.11 U9.14 U9.15 U9.16
A_3.3V: C79.1 C80.1 C81.1 C82.1 J6.12 R97.2 R146.1 R149.2 U9.21 U9.22 U9.23
AC_L_SAMPLE: C67.1 C148.1 C149.1 C150.1 C151.1 CON7.1 CON7.2 CON7.3 CON7.4 CON8.1 CON8.2 CON8.3 CON8.4 CON9.1 CON9.2 CON9.3 CON9.4 R133.1 U16.10 U16.11 U16.12 U16.13
AC_SW: L1.3 Q51.2 Q52.2 Q61.1 Q62.1
CAN+: J1.4
CAN+5V: J1.1 J4.1
CAN-: J1.2
CAN_GND: J1.3 J4.2
CLAMP1: R4.2 R5.2 R17.2 U1.7
CLAMP2: R35.2 R36.2 R37.2 U3.7
CLAMP3: R58.2 R62.2 R64.2 U4.7
CLAMP4: R80.2 R84.2 R90.2 U6.7
CLAMP5: R15.2 R16.2 U2.7
CLAMP6: R49.2 R50.2 U5.7
DC+: C43.1 C44.1 C47.1 C47.3 C55.1 CON1.1 CON1.2 CON1.3 CON1.4 Q11.1 Q12.1 Q13.1 R109.1 R125.1
DC-: C51.2 C52.2 C53.2 C53.4 C71.2 CON3.1 CON3.2 CON3.3 CON3.4 Q41.2 Q42.2 Q43.2 R86.1 R168.1
DC_H_+: J6.4 R81.2
DC_H_-: J6.6 R82.2
DC_L_+: J6.3 R161.2
DC_L_-: J6.5 R117.2
DC_N: C45.2 C46.2 C47.2 C47.4 C49.1 C50.1 C53.1 C53.3 C55.2 C67.2 C71.1 C148.2 C149.2 C150.2 C151.2 CON14.1 CON14.2 CON14.3 CON14.4 CON15.1 CON15.2 CON15.3 CON15.4 CON16.1 CON16.2 CON16.3 CON16.4 CON17.1 CON17.2 CON17.3 CON17.4 CON18.1 CON18.2 CON18.3 CON18.4 Q21.2 Q22.2 Q23.2 Q31.1 Q32.1 Q33.1 R87.1 R99.1 R100.1 R130.2 R131.1 R139.1
DRV_COM1: C4.1 C7.2 C83.2 C84.1 C85.2 C90.1 C91.1 R12.2 R14.2 R24.2 U11.6
DRV_COM2: C15.1 C20.2 C100.2 C101.1 C102.2 C107.1 C108.1 R42.2 R43.2 R44.2 U12.6
DRV_COM3: C21.1 C29.2 C109.2 C110.1 C111.2 C119.1 C120.1 R69.2 R71.2 R73.2 U13.6
DRV_COM4: C30.1 C40.2 C127.2 C128.1 C129.2 C137.1 C138.1 R122.2 R123.2 R124.2 U15.6
DRV_COM5: C12.2 C18.1 C116.2 C117.1 C118.2 C125.1 C126.1 R32.2 R34.2 U14.6
DRV_COM6: C32.2 C35.1 C134.2 C135.1 C136.2 C143.1 C144.1 R61.2 R63.2 U17.6
DRV_G11: Q11.4 R9.1 R11.2 R17.1 R91.2 R94.2
DRV_G12: Q12.4 R1.1 R2.2 R5.1 R93.2 R173.2
DRV_G13: Q13.4 R4.1 R6.1 R8.2 R92.2 R169.2
DRV_G21: Q21.4 R27.1 R28.2 R37.1 R174.2 R177.2
DRV_G22: Q22.4 R29.1 R31.2 R36.1 R176.2 R178.2
DRV_G23: Q23.4 R35.1 R38.1 R40.2 R170.2 R175.2
DRV_G31: Q31.4 R45.1 R48.2 R64.1 R179.2 R182.2
DRV_G32: Q32.4 R51.1 R55.2 R62.1 R118.2 R183.2
DRV_G33: Q33.4 R58.1 R66.1 R68.2 R171.2 R180.2
DRV_G41: Q41.4 R74.1 R77.2 R90.1 R184.2 R187.2
DRV_G42: Q42.4 R78.1 R79.2 R84.1 R186.2 R188.2
DRV_G43: Q43.4 R80.1 R95.1 R121.2 R172.2 R185.2
DRV_G51: C56.2 Q51.4 R16.1 R18.2 R83.2
DRV_G52: C57.2 Q52.4 R15.1 R23.2 R85.2
DRV_G61: C61.2 Q61.4 R50.1 R53.2 R88.2
DRV_G62: C62.2 Q62.4 R49.1 R59.2 R89.2
DRV_GATE1: R22.1 U1.6
DRV_GATE2: R39.1 U3.6
DRV_GATE3: R67.1 U4.6
DRV_GATE4: R96.1 U6.6
DRV_Q1_+15V: C83.1 C84.2 C85.1 R189.1 U11.7
DRV_Q1_-3V: C5.1 C7.1 C90.2 C91.2 U1.8 U11.5
DRV_Q2_+15V: C100.1 C101.2 C102.1 R191.1 U12.7
DRV_Q2_-3V: C17.1 C20.1 C107.2 C108.2 U3.8 U12.5
DRV_Q3_+15V: C109.1 C110.2 C111.1 R193.1 U13.7
DRV_Q3_-3V: C25.1 C29.1 C119.2 C120.2 U4.8 U13.5
DRV_Q4_+15V: C127.1 C128.2 C129.1 R194.1 U15.7
DRV_Q4_-3V: C34.1 C40.1 C137.2 C138.2 U6.8 U15.5
DRV_Q5_+15V: C116.1 C117.2 C118.1 R190.1 U14.7
DRV_Q5_-3V: C16.2 C18.2 C125.2 C126.2 U2.8 U14.5
DRV_Q6_+15V: C134.1 C135.2 C136.1 R192.1 U17.7
DRV_Q6_-3V: C33.2 C35.2 C143.2 C144.2 U5.8 U17.5
DRV_S11: C19.1 Q11.3 R12.1 R94.1
DRV_S12: C54.1 Q12.3 R14.1 R173.1
DRV_S13: C39.1 Q13.3 R24.1 R169.1
DRV_S21: C64.1 Q21.3 R42.1 R177.1
DRV_S22: C66.1 Q22.3 R43.1 R178.1
DRV_S23: C65.1 Q23.3 R44.1 R170.1
DRV_S31: C70.1 Q31.3 R69.1 R182.1
DRV_S32: C146.1 Q32.3 R71.1 R183.1
DRV_S33: C145.1 Q33.3 R73.1 R171.1
DRV_S41: C162.1 Q41.3 R122.1 R187.1
DRV_S42: C164.1 Q42.3 R123.1 R188.1
DRV_S43: C163.2 Q43.3 R124.1 R172.1
DRV_S51: C56.1 Q51.3 R32.1 R83.1
DRV_S52: C57.1 Q52.3 R34.1 R85.1
DRV_S61: C61.1 Q61.3 R61.1 R88.1
DRV_S62: C62.1 Q62.3 R63.1 R89.1
FAN_12V: CON101.6 CON102.6 CON103.1
FAN_GND: CON101.1 CON102.1 CON103.2 CON103.3
GATE5: R18.1 R23.1 U2.6
GATE6: R53.1 R59.1 U5.6
GGND: C86.2 C87.2 C88.1 C89.2 C103.2 C104.2 C105.1 C106.2 C112.2 C113.2 C114.1 C115.2 C121.2 C122.2 C123.1 C124.2 C130.2 C131.2 C132.1 C133.2 C139.2 C140.2 C141.1 C142.2 J5.6 U11.2 U12.2 U13.2 U14.2 U15.2 U17.2
IGND: C157.2 J2.1 J5.2
IL+: J6.1 R75.1
IL-: J6.2 R76.1
MID_N: Q31.2 Q32.2 Q33.2 Q41.1 Q42.1 Q43.1 Q61.2 Q62.2
MID_P: Q11.2 Q12.2 Q13.2 Q21.1 Q22.1 Q23.1 Q51.1 Q52.1
NETC1_2: C1.2 C2.1 R3.2 U1.1
NETC3_2: C3.2 R7.2 R10.2 U1.2
NETC4_2: C4.2 C5.2 R189.2 U1.5
NETC8_2: C8.2 C9.1 R19.2 U2.1
NETC10_2: C10.2 R21.2 R25.2 U2.2
NETC11_2: C11.2 C13.1 R26.2 U3.1
NETC12_1: C12.1 C16.1 R190.2 U2.5
NETC14_2: C14.2 R30.2 R33.2 U3.2
NETC15_2: C15.2 C17.2 R191.2 U3.5
NETC19_2: C19.2 R91.1
NETC21_2: C21.2 C25.2 R193.2 U4.5
NETC22_2: C22.2 C23.1 R41.2 U4.1
NETC24_2: C24.2 R46.2 R52.2 U4.2
NETC26_2: C26.2 C27.1 R54.2 U5.1
NETC30_2: C30.2 C34.2 R194.2 U6.5
NETC31_2: C31.2 R57.2 R60.2 U5.2
NETC32_1: C32.1 C33.1 R192.2 U5.5
NETC36_2: C36.2 C37.1 R65.2 U6.1
NETC38_2: C38.2 R70.2 R72.2 U6.2
NETC39_2: C39.2 R92.1
NETC43_2: C43.2 C44.2 C45.1 C46.1 R127.2 R128.1
NETC49_2: C49.2 C50.2 C51.1 C52.1 R165.2 R167.2
NETC54_2: C54.2 R93.1
NETC64_2: C64.2 R174.1
NETC65_2: C65.2 R175.1
NETC66_2: C66.2 R176.1
NETC70_2: C70.2 R179.1
NETC86_1: C86.1 C87.1 C88.2 C89.1 R147.2 U11.1
NETC92_1: C92.1 Q15.3 R145.1 U9.7
NETC103_1: C103.1 C104.1 C105.2 C106.1 R152.2 U12.1
NETC112_1: C112.1 C113.1 C114.2 C115.1 R153.2 U13.1
NETC121_1: C121.1 C122.1 C123.2 C124.1 R154.2 U14.1
NETC130_1: C130.1 C131.1 C132.2 C133.1 R155.2 U15.1
NETC139_1: C139.1 C140.1 C141.2 C142.1 R156.2 U17.1
NETC145_2: C145.2 R180.1
NETC146_2: C146.2 R118.1
NETC152_1: C152.1 C153.1 R97.1 U16.1
NETC154_1: C154.1 U16.4
NETC155_1: C155.1 R75.2 R98.1
NETC162_2: C162.2 R184.1
NETC163_1: C163.1 R185.1
NETC164_2: C164.2 R186.1
NETD1_1: D1.1 R1.2
NETD1_2: D1.2 D2.2 D3.2 R2.1 R8.1 R11.1 R22.2
NETD2_1: D2.1 R6.2
NETD3_1: D3.1 R9.2
NETD6_1: D6.1 R27.2
NETD6_2: D6.2 D7.2 D8.2 R28.1 R31.1 R39.2 R40.1
NETD7_1: D7.1 R29.2
NETD8_1: D8.1 R38.2
NETD9_1: D9.1 R45.2
NETD9_2: D9.2 D10.2 D13.2 R48.1 R55.1 R67.2 R68.1
NETD10_1: D10.1 R51.2
NETD13_1: D13.1 R66.2
NETD14_1: D14.1 R74.2
NETD14_2: D14.2 D15.2 D16.2 R77.1 R79.1 R96.2 R121.1
NETD15_1: D15.1 R78.2
NETD16_1: D16.1 R95.2
NETL1_1: L1.1 L1.4
NETL1_2: L1.2 L2.2
NETL2_1: L2.1 L2.4
NETL2_3: L2.3 U16.6 U16.7 U16.8 U16.9
NETQ15_1: Q15.1 R149.1 R151.2
NETR81_1: R81.1 R114.2
NETR82_1: R82.1 R105.2
NETR86_2: R86.2 R106.1
NETR87_2: R87.2 R120.1
NETR98_2: R98.2 U16.3
NETR100_2: R100.2 R101.1
NETR101_2: R101.2 R102.1
NETR102_2: R102.2 R103.1
NETR103_2: R103.2 R104.1
NETR104_2: R104.2 R105.1
NETR106_2: R106.2 R107.1
NETR107_2: R107.2 R108.1
NETR108_2: R108.2 R115.1
NETR109_2: R109.2 R110.1
NETR110_2: R110.2 R111.1
NETR111_2: R111.2 R112.1
NETR112_2: R112.2 R113.1
NETR113_2: R113.2 R114.1
NETR115_2: R115.2 R116.1
NETR116_2: R116.2 R117.1
NETR120_2: R120.2 R157.1
NETR125_2: R125.2 R126.1
NETR126_2: R126.2 R127.1
NETR128_2: R128.2 R129.1
NETR129_2: R129.2 R130.1
NETR131_2: R131.2 R132.1
NETR132_2: R132.2 R165.1
NETR133_2: R133.2 R134.1
NETR134_2: R134.2 R135.1
NETR135_2: R135.2 R136.1
NETR136_2: R136.2 R137.1
NETR137_2: R137.2 R138.1
NETR139_2: R139.2 R140.1
NETR140_2: R140.2 R141.1
NETR141_2: R141.2 R142.1
NETR142_2: R142.2 R143.1
NETR143_2: R143.2 R144.1
NETR146_2: R146.2 R148.2 U9.19
NETR150_2: R150.2 U9.8
NETR157_2: R157.2 R158.1
NETR158_2: R158.2 R159.1
NETR159_2: R159.2 R160.1
NETR160_2: R160.2 R161.1
NETR166_1: R166.1 R168.2
NETR166_2: R166.2 R167.1
PWM-1A: J3.2 R57.1
PWM-1B: J3.4 R21.1
PWM-2A: J3.6 R7.1
PWM-2B: J3.8 R30.1
PWM-3A: J3.5 R46.1
PWM-3B: J3.7 R70.1
RELAY: J3.1
VA+5V: C75.1 C77.2 C78.2 C97.1 C98.1 C99.1 J6.8 R3.1 R19.1 R26.1 R41.1 R54.1 R65.1 R145.2 U8.1 U9.2 U9.3 U9.10 U9.11
VL: J6.7 R138.2
VN: J6.9 R144.2
VS+15V: J4.4
XRS: R148.1 R150.1

Pads without a net: CON101 2 3 4 5; CON102 2 3 4 5; FD1 0; FD2 0; FD3 0; FD4 0; J4 3; J5 3 4 7 8; NOREF 1; NOREF#2 1; NOREF#4 1; NOREF#5 1; NOREF#6 1; NOREF#10 1; NOREF#11 1; NOREF#13 1; NOREF#17 1; NOREF#18 1; NOREF#19 1; NOREF#20 1; NOREF#21 1; NOREF#23 1; NOREF#25 1; NOREF#26 1; NOREF#29 1; NOREF#30 1; NOREF#31 1; NOREF#33 1; NOREF#34 1; NOREF#35 1; NOREF#37 1; NOREF#38 1; U9 4 5 17 18 20; U16 5

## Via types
v1: diameter 0.61, hole 0.305, TOP to BOTTOM, 1030 vias

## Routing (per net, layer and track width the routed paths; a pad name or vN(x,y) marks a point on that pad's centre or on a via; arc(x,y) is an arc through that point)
+14V: length 87
  TOP w0.762: J2.2 95.11,4.95 C157.1 96.77,3.28 117.96,3.28 124,9.33 150.83,9.33 152.78,11.28 163.58,11.28 J5.1
AGND: length 100.7
  TOP w0.381: R76.2 382.17,5.57 C155.2 v1(386.77,5.57) ; U16.2 404.08,3.86 403.39,3.17 395.21,3.17 393.44,4.95 C152.2 388.74,4.81 v1(387.53,4.81) ; v1(386.77,5.57) 386.74,5.55 C153.2 ; v1(386.77,5.57) 386.77,6.07 C154.2
  TOP w0.508: v1(290.08,5.07) 290.06,5.06 C92.2 288.92,5.03 R151.1 ; Q15.2 v1(281.83,4.87)
  TOP w0.762: C75.2 208.05,9.25 v1(208.05,9.09)
  BOTTOM w0.381: U9.6 289.56,6.76 v1(290.07,6.25) ; U9.9 289.5,8.71 289.51,8.73 289.52,8.73 289.78,8.98 289.82,8.98 v1(290.08,9.24)
  BOTTOM w0.508: v1(309.14,11.15) 309.14,11.15 C94.2 ; R99.2 v1(240.93,21.6)
  BOTTOM w0.762: 156,8.71 156,12.64 158.32,14.97 174.4,14.97 183.31,6.06 207.41,6.06 208.19,6.85 208.19,8.95 v1(208.05,9.09)
  vias: v1(79.83,171.82) v1(87.14,172.05) v1(103.17,60.95) v1(110.93,61.52) v1(164.78,172.02) v1(172.49,172.05) v1(174.3,60.33) v1(181.76,60.27) v1(229.5,60.44) v1(232.46,171.75) v1(236.52,60.72) v1(239.91,171.95) v1(281.96,9.03) v1(291.08,8.64) v1(291.08,7.75) v1(291.08,6.73) v1(291.08,5.71) v1(291.97,8.64) v1(291.97,7.75) v1(291.97,6.73) v1(291.97,5.71)
P6.5V: length 64.6
  BOTTOM w0.762: J5.10 154.4,7.77 154.4,12.49 157.9,15.99 174.82,15.99 183.43,7.37 v1(206.98,7.37)
P15V: length 742.3
  TOP w0.762: v1(260.89,179) 257.56,182.33 200.26,182.33 v1(198.9,180.97)
  GND02 w0.762: v1(198.9,180.97) 177.96,180.97 176.42,182.52 176.42,203 167.03,212.39 37.17,212.39 31.9,207.12 31.9,181.97 36.85,177.03 v1(37.13,177.03)
  ART03 w0.762: v1(57.57,64.05) 57.56,64.05 57.56,96.27 70.39,109.1 70.39,123.55 55.44,138.51 55.44,158.54 v1(59.83,162.93) ; v1(107.98,11.61) 111.82,11.61 113.32,13.11 146.12,13.11 148.71,10.52 159.27,10.52 J5.5 161.15,8.78 161.15,10.54 166.06,15.46 191.18,15.46 199.4,23.68 v1(217.39,23.68)
  BOTTOM w0.762: R147.1 v1(59.83,162.93) 60.2,162.93 61.7,164.43 61.7,174.99 59.87,176.83 37.34,176.83 v1(37.13,177.03) ; v1(198.9,180.97) 198.9,179.07 R152.1 ; 220.53,22.46 218.61,22.46 v1(217.39,23.68) ; v1(107.98,11.61) 106.29,11.61 105.52,12.37 105.52,17.17 102.74,19.96 68.86,19.96 54.27,34.55 54.27,57.6 57.56,60.9 57.56,64.04 v1(57.57,64.05) R155.1 ; R156.1 240.81,30.1 237.94,30.1 230.3,22.46 220.53,22.46 ; R154.1 v1(260.89,179)
  BOTTOM w0.78: v1(217.39,23.68) 217.39,24.34 218.35,25.3 218.35,48.34 R153.1 ; 220.53,22.46 220.53,22.46
A_1.2V:
  vias: v1(278.66,5.64) v1(278.66,5) v1(279.39,5.64) v1(279.39,5) v1(306.22,8.2) v1(307.11,8.23) v1(307.87,8.2) v1(308.76,8.2)
A_3.3V: length 92
  TOP w0.508: R149.2 293.24,3.63 R146.1 v1(295.9,4.42) ; v1(304.57,6.58) 316.57,6.58 322.33,12.34 334.44,12.34 337.75,9.03 368.93,9.03 374.61,3.35 383.65,3.35 384.97,4.68 R97.2
  vias: v1(303.47,6.58)
AC_L_SAMPLE: length 43.2
  BOTTOM w0.508: 409.84,14.35 407.42,11.94 385.58,11.94 378.86,5.22 R133.1
  vias: v1(415.21,16.68) v1(415.21,11.68) v1(415.46,18.21) v1(415.46,13.21) v1(416.15,15.58) v1(416.15,10.58) v1(416.48,18.84) v1(416.48,13.84) v1(417.62,15.54) v1(417.62,10.54) v1(417.88,18.71) v1(417.88,13.71) v1(418.39,16.43) v1(418.39,11.43) v1(418.51,17.83) v1(418.51,12.83) v1(425.11,16.68) v1(425.11,11.68) v1(425.36,18.21) v1(425.36,13.21) v1(426.05,15.58) v1(426.05,10.58) v1(426.38,18.84) v1(426.38,13.84) v1(427.52,15.54) v1(427.52,10.54) v1(427.78,18.71) v1(427.78,13.71) v1(428.29,16.43) v1(428.29,11.43) v1(428.41,17.83) v1(428.41,12.83) v1(430.58,16.94) v1(430.58,11.94) v1(430.83,18.46) v1(430.83,13.46) v1(431.52,15.83) v1(431.52,10.83) v1(431.85,19.1) v1(431.85,14.1) v1(432.99,15.79) v1(432.99,10.79) v1(433.24,18.97) v1(433.24,13.97) v1(433.75,16.68) v1(433.75,11.68) v1(433.88,18.08) v1(433.88,13.08) v1(440.48,16.94) v1(440.48,11.94) v1(440.73,18.46) v1(440.73,13.46) v1(441.42,15.83) v1(441.42,10.83) v1(441.75,19.1) v1(441.75,14.1) v1(442.89,15.79) v1(442.89,10.79) v1(443.14,18.97) v1(443.14,13.97) v1(443.65,16.68) v1(443.65,11.68) v1(443.78,18.08) v1(443.78,13.08) v1(445.69,16.94) v1(445.69,11.94) v1(445.94,18.46) v1(445.94,13.46) v1(446.63,15.83) v1(446.63,10.83) v1(446.96,19.1) v1(446.96,14.1) v1(448.1,15.79) v1(448.1,10.79) v1(448.36,18.97) v1(448.36,13.97) v1(448.87,16.68) v1(448.87,11.68) v1(448.99,18.08) v1(448.99,13.08) v1(455.59,16.94) v1(455.59,11.94) v1(455.84,18.46) v1(455.84,13.46) v1(456.48,164.59) v1(456.48,133.48) v1(456.48,101.73) v1(456.48,69.98) v1(456.48,38.86) v1(456.53,15.83) v1(456.53,10.83) v1(456.61,163.58) v1(456.61,132.46) v1(456.61,100.71) v1(456.61,68.96) v1(456.61,37.85) v1(456.86,19.1) v1(456.86,14.1) v1(457.5,165.23) v1(457.5,163.07) v1(457.5,134.11) v1(457.5,131.95) v1(457.5,102.36) v1(457.5,100.2) v1(457.5,70.61) v1(457.5,68.45) v1(457.5,39.5) v1(457.5,37.34) v1(458,15.79) v1(458,10.79) v1(458.26,18.97) v1(458.26,13.97) v1(458.51,164.72) v1(458.51,163.58) v1(458.51,133.6) v1(458.51,132.46) v1(458.51,101.85) v1(458.51,100.71) v1(458.51,70.1) v1(458.51,68.96) v1(458.51,38.99) v1(458.51,37.85) v1(458.77,16.68) v1(458.77,11.68) v1(458.89,18.08) v1(458.89,13.08)
AC_SW:
  vias: v1(218.01,84.97) v1(218.01,83.27) v1(218.92,82.45) v1(220.62,82.45) v1(224.16,150.27) v1(225.53,150.27) v1(239.33,84.97) v1(239.33,83.27) v1(240.24,82.45) v1(241.94,82.45) v1(245.37,150.27) v1(246.74,150.27) v1(283.78,136.45) v1(283.78,135.18) v1(284.16,137.72) v1(284.28,134.29) v1(285.05,138.48) v1(285.3,133.53) v1(286.44,138.99) v1(286.82,133.15) v1(287.84,138.99) v1(288.48,133.15) v1(289.24,138.99) v1(289.75,133.15) v1(290.76,138.99) v1(290.98,133.13) v1(292.16,138.99) v1(292.29,133.15) v1(293.56,138.99) v1(293.81,133.15) v1(295.08,138.86) v1(295.59,133.4) v1(296.48,138.1) v1(296.6,134.16) v1(297.11,136.96) v1(297.24,135.56)
CAN+5V: length 81.3
  ART04 w0.762: J1.1 218.26,3.56 153.63,3.56 151.01,6.17 J4.1
CAN_GND: length 87.4
  ART04 w0.762: J1.3 219.58,2.34 153.07,2.34 150.65,4.75 149.25,4.75 149.23,4.77 137.48,4.77 J4.2
CLAMP1: length 67.9
  ART04 w0.508: v1(84.79,156.84) 84.79,161.27 82.37,163.69 v1(82.31,163.69)
  BOTTOM w0.508: R5.2 93.63,156.06 86.55,156.06 85.76,156.84 v1(84.79,156.84) ; v1(82.31,163.69) 82.28,163.69 82.25,163.67 U1.7 ; v1(84.79,156.84) 82.74,156.84 80.86,158.72 79.26,158.72 77.96,160.02 75.94,160.02 74.79,158.88 R17.2 ; v1(84.79,156.84) 84.79,156.29 86.09,154.99 92.18,154.99 93.3,153.87 102.25,153.87 103.54,155.17 R4.2
CLAMP2: length 69.8
  BOTTOM w0.381: R35.2 188.53,155.81 188.53,157.91 187.94,158.49 185.81,158.49 184.18,156.86 171.83,156.86 170.61,158.07 166.63,158.07 165.93,158.78 165.25,158.78 165.21,158.82 164.87,158.82 164.32,159.37 163.97,159.37
  BOTTOM w0.508: 161.22,158.63 161.22,158.92 161.27,158.97 ; 161.22,158.63 161.22,156.49 162.77,154.94 R36.2 ; 161.22,158.63 160.88,158.97 ; 160.88,158.97 160.55,159.3 143.22,159.3 141.91,157.99 R37.2 ; 160.88,158.97 161.27,158.97 ; 161.27,158.97 163.57,158.97 164.27,159.66 164.27,162.9 165.31,163.94 166.6,163.94 167.11,163.44 U3.7
CLAMP3: length 63.4
  ART05 w0.508: v1(182.15,67.15) 182.15,75.92 183.93,77.7 v1(184.03,77.7)
  BOTTOM w0.508: R62.2 183.15,77.7 v1(184.03,77.7) ; v1(184.03,77.7) 184.08,77.75 184.08,78.11 183.57,78.61 174.33,78.61 173.59,77.88 173.59,76.96 172.39,75.76 162.76,75.76 R64.2 ; v1(184.03,77.7) 184.03,77.37 185.07,76.33 191.56,76.33 193.79,78.56 200.32,78.56 R58.2 ; U4.7 179.31,68.24 180.4,67.15 v1(182.15,67.15)
CLAMP4: length 59.3
  ART05 w0.508: 112.98,75.97 112.98,75.21 112.48,74.7 111.93,74.7 108.61,71.37 v1(108.61,69.29) ; 112.98,75.97 v1(113.04,76.02) 113.09,75.97 114.64,75.97 115.93,74.68 v1(116.44,74.68) ; 112.98,75.97 110.72,75.97 v1(110.09,75.34)
  BOTTOM w0.508: R84.2 113.04,77.09 v1(113.04,76.02) ; U6.7 v1(108.61,69.29) ; v1(110.09,75.34) 110.09,75.08 109.17,74.16 107.35,74.16 105.86,75.65 92.93,75.65 R90.2 ; v1(116.44,74.68) 116.67,74.68 117.61,73.74 131.98,73.74 132.65,74.41 R80.2
CLAMP5: length 30.3
  ART04 w0.508: v1(237.58,156.64) 236.56,157.65 236.56,159.36 v1(234.89,161.04) 233.87,160.02 231.78,160.02 v1(230.89,160.91)
  BOTTOM w0.508: v1(230.89,160.91) 221.37,160.91 220.17,159.71 R16.2 ; v1(237.58,156.64) 238.31,156.64 239.9,155.04 R15.2 ; U2.7 v1(234.89,161.04)
CLAMP6: length 31.6
  ART05 w0.508: v1(234.43,71.12) 233.96,71.58 v1(233.96,75.45) v1(236.5,75.45)
  BOTTOM w0.508: R50.2 232.26,77.15 v1(233.96,75.45) ; R49.2 253.73,77.27 252.51,78.48 247.95,78.48 244.92,75.45 v1(236.5,75.45) ; U5.7 v1(234.43,71.12)
DC+: length 33.6
  BOTTOM w0.508: R109.1 108.59,196.46 104.14,192.01 C44.1 ; C43.1 66.54,191.92 ; 74.16,193.12 75.11,194.07 75.11,196.38 R125.1
  vias: v1(41.54,199.35) v1(41.54,189.45) v1(41.58,200.82) v1(41.58,190.92) v1(42.43,198.58) v1(42.43,188.68) v1(42.69,201.76) v1(42.69,191.86) v1(43.83,198.46) v1(43.83,188.56) v1(44.21,201.5) v1(44.21,191.6) v1(44.72,199.09) v1(44.72,189.19) v1(44.85,200.49) v1(44.85,190.59) v1(46.54,199.35) v1(46.54,189.45) v1(46.58,200.82) v1(46.58,190.92) v1(47.43,198.58) v1(47.43,188.68) v1(47.69,201.76) v1(47.69,191.86) v1(48.83,198.46) v1(48.83,188.56) v1(49.21,201.5) v1(49.21,191.6) v1(49.72,199.09) v1(49.72,189.19) v1(49.85,200.49) v1(49.85,190.59) v1(68.86,192.59) v1(68.82,191.11) v1(69.71,190.35) v1(69.97,193.52) v1(71.11,190.22) v1(71.49,193.27) v1(72,190.86) v1(72.13,192.25) v1(87.09,146.3) v1(88.79,146.3) v1(89.61,148.91) v1(89.61,147.2) v1(100.02,192.67) v1(99.99,191.2) v1(100.88,190.43) v1(101.13,193.61) v1(102.27,190.31) v1(102.65,193.36) v1(103.16,190.94) v1(103.29,192.34) v1(108.3,146.3) v1(110,146.3) v1(110.82,148.91) v1(110.82,147.2) v1(118.16,189.11) v1(118.16,178.91) v1(118.24,188.02) v1(118.24,177.82) v1(118.89,189.75) v1(118.89,179.55) v1(119.23,187.47) v1(119.23,177.27) v1(119.94,189.51) v1(119.94,179.31) v1(120.28,188.16) v1(120.28,177.96) v1(121.63,166.12) v1(121.69,164.9) v1(122.58,164.13) v1(122.84,167.31) v1(123.98,164.01) v1(124.36,167.06) v1(124.87,164.64) v1(125,166.04) v1(129.51,146.3) v1(131.21,146.3)
DC-: length 12.7
  BOTTOM w0.508: 73.41,43.43 69.21,43.43 C52.2
  BOTTOM w0.762: R86.1 100.34,44.68 C51.2
  vias: v1(34.25,25.39) v1(34.21,23.91) v1(34.25,20.39) v1(34.21,18.91) v1(35.1,23.15) v1(35.1,18.15) v1(35.35,26.33) v1(35.35,21.33) v1(36.49,23.02) v1(36.49,18.02) v1(36.88,26.07) v1(36.88,21.07) v1(37.38,23.66) v1(37.38,18.66) v1(37.51,25.06) v1(37.51,20.06) v1(44.15,25.39) v1(44.11,23.91) v1(44.15,20.39) v1(44.11,18.91) v1(45,23.15) v1(45,18.15) v1(45.25,26.33) v1(45.25,21.33) v1(46.39,23.02) v1(46.39,18.02) v1(46.78,26.07) v1(46.78,21.07) v1(47.28,23.66) v1(47.28,18.66) v1(47.41,25.06) v1(47.41,20.06) v1(66.56,45.16) v1(66.52,43.69) v1(67.41,42.93) v1(67.67,46.1) v1(68.81,42.8) v1(69.19,45.85) v1(69.7,43.44) v1(69.83,44.83) v1(82.06,86.42) v1(83.43,86.42) v1(98.42,45.34) v1(98.38,43.87) v1(99.27,43.11) v1(99.52,46.28) v1(100.67,42.98) v1(101.05,46.03) v1(101.55,43.62) v1(101.68,45.01) v1(103.38,86.42) v1(104.75,86.42) v1(117.58,53.28) v1(117.58,43.08) v1(117.71,52.26) v1(117.71,42.06) v1(118.6,53.91) v1(118.6,51.75) v1(118.6,43.71) v1(118.6,41.55) v1(119.61,53.41) v1(119.61,52.26) v1(119.61,43.21) v1(119.61,42.06) v1(120.34,65.86) v1(120.4,64.64) v1(121.29,63.88) v1(121.55,67.06) v1(122.69,63.75) v1(123.07,66.8) v1(123.58,64.39) v1(123.71,65.79) v1(124.7,86.42) v1(126.07,86.42)
DC_H_+: length 533.1
  TOP w0.254: v1(98.91,15.22) 98.59,15.54 67.17,15.54 67.15,15.56 66.85,15.86 66.66,16.04 50.01,32.7 50.01,97.46 64,111.44 64,118.55 49.03,133.52 49.03,173.82 46.16,176.7 44.68,176.7 34.3,187.08 34.3,187.11 34.19,187.22 34.19,204.23 39.5,209.55 136.19,209.55 136.2,209.56 141.55,209.56 v1(141.91,209.92)
  ART03 w0.254: J6.4 263.82,7.33 263.82,7.72 263,8.54 260.07,8.54 253.43,1.9 119.5,1.9 112.83,8.56 106.06,8.56 99.41,15.22 v1(98.91,15.22)
  BOTTOM w0.254: R81.2 v1(141.91,209.92)
DC_H_-: length 535.6
  TOP w0.254: v1(144.06,209.92) 143.08,208.95 136.2,208.95 39.62,208.95 34.7,204.02 34.7,187.43 34.81,187.33 34.81,187.29 44.89,177.21 46.37,177.21 49.54,174.03 49.54,133.73 64.51,118.76 64.51,111.23 50.52,97.25 50.52,35.01 50.52,32.91 66.87,16.55 67.06,16.36 67.36,16.07 99.7,16.07 v1(99.79,15.97)
  ART03 w0.254: v1(99.79,15.97) 99.79,15.55 106.27,9.07 113.04,9.07 119.71,2.41 253.12,2.41 259.9,9.19 263.16,9.19 264.56,7.8 264.56,6.88 264.9,6.53 J6.6
  BOTTOM w0.254: R82.2 v1(144.06,209.92)
